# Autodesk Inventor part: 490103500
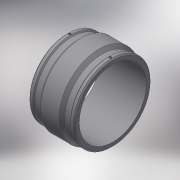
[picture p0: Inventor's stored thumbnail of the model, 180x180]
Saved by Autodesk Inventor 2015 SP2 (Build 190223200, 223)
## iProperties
Created: 2017-06
Part Number: 490103500
Material: Generic
Description: PLASSON COUPLER 500
Document SubType Name: Modeling
Designer: KIM
Mass: 16398.8 g
Surface Area: 10528.4 cm^2
Volume: 16398.8 cm^3
Density: 1 g/cm^3
Appearance: Default
Author: KIM
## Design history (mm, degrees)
derived "490103.ipt"
feature "Solid1::490103.ipt"
tag "TaggingFeature1"
body "Solid1"
other parameters: "d22" = 566, "d23" = 603, "d24" = 549.02, "d25" = 135 deg, "d26" = 136, "d27" = 135 deg, "d29" = 283, "d35" = 15, "d39" = 0, "d40" = 4, "d41" = 14, "d42" = 0, "d43" = 135 deg, "d44" = 37.4, "d46" = 6, "d47" = 0, "D_" = 603, "A_" = 283, "d_2" = 12
